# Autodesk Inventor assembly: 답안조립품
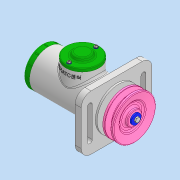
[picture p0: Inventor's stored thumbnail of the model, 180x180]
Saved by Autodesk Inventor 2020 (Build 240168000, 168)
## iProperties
Created: 2021-07
Part Number: 답안조립품
Document SubType Name: Assembly
Designer: MIRAE
Author: MIRAE
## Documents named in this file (20)
- C:\Users\MIRAE\Desktop\710706V1006\답안조립품.iam
- C:\Users\MIRAE\Desktop\710706V1006\본체.ipt
- C:\Users\MIRAE\Desktop\710706V1006\축.ipt
- C:\Users\MIRAE\Desktop\710706V1006\베어링 15 x 35 x 11.ipt
- C:\Users\MIRAE\Desktop\710706V1006\부시1.ipt
- C:\Users\MIRAE\Desktop\710706V1006\멈춤링 35 x 1.6.ipt
- C:\Users\MIRAE\Desktop\710706V1006\부시2.ipt
- C:\Users\MIRAE\Desktop\710706V1006\와셔 10 x 21.ipt
- C:\Users\MIRAE\Desktop\710706V1006\너트 M10.ipt
- C:\Users\MIRAE\Desktop\710706V1006\사이드 커버.ipt
- 사이드 커버.ipt
- C:\Users\MIRAE\Desktop\710706V1006\멈춤링 15 x 1.ipt
- C:\Users\MIRAE\Desktop\710706V1006\오일 실 15 25 7.ipt
- C:\Users\MIRAE\Desktop\710706V1006\키 4 x 4 x 18.ipt
- C:\Users\MIRAE\Desktop\710706V1006\V-벨트풀리.ipt
- C:\Users\MIRAE\Desktop\710706V1006\와셔 4 x 16.ipt
- C:\Users\MIRAE\Desktop\710706V1006\볼트 M4 x 10.ipt
- C:\Users\MIRAE\Desktop\710706V1006\탑 커버.ipt
- C:\Users\MIRAE\Desktop\710706V1006\십자볼트 M3 x 10.ipt
- C:\Users\MIRAE\Desktop\710706V1006\와셔 3 x 6.ipt
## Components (2 placed, 2 different names)
1. V-벨트풀리:1
2. ISO 4017 M4 x 10:1
